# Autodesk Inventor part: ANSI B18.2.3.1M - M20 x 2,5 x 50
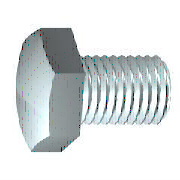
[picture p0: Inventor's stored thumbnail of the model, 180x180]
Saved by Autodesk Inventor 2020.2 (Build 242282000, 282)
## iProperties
Manager: www.cadconsulting.pl
Company: Fabian Stasiak CAD Consulting
Created: 2006-02
Part Number: ANSI B18.2.3.1M - M20 x 2,5 x 50
Material: Stal, miękka
Description: Metryczny Śruba ze łbem sześciokątnym o zmniejszonych wymiarach
Document SubType Name: Modeling
Standard: ANSI B18.2.3.1M
Designer: F.Stasiak
Standards Organization: ANSI
Language: pl-PL
Size Designation: M20 x 2,5 x 50
Categories: <MemberInstance><Categories><Category DisplayName="Mocowania" InternalName="e4da775c-781d-43d5-af7c-5136215cf5a6" Mnemonic="FSTN"><Category DisplayName="Śruby"
Density: 1 g/cm^3
Appearance: Stal
Author: F.Stasiak
Subject: Zbiór ćwiczeń. Autodesk Inventor 2020. Kurs podstawowy
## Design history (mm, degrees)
sketch "Szkic1"
  geometry: L1 (0, 13.85)-(0, 10); L2 (6.2, 10)-(50, 10); L3 (50, 10)-(50, 0); L4 (50, 0)-(-0.8, 0); L5 (-5.88, 0)-(65.24, 0) reference; L6 (-0.8, 0)-(-0.8, 13.85); L7 (-0.8, 13.85)-(0, 13.85); L8 (6.2, 10)-(4.666, 10); L9 (4.666, 10)-(0, 10); L10 (0, -1.385)-(0, 18.005) reference
  constraints: 16 end point, 2 collinear, 2 perpendicular, 1 parallel
  dimensions: "d0" = 50 distance between parallel lines of L3 L1 (= NLG); "d1" = 43.8 distance from line of L2.start L3 (= GEL); "d2" = 20 diameter of L2 L4 (= GD); "d9" = 0.8001 distance between parallel lines of L6 L1 (computed from SD); "d10" = 27.7 diameter of L7 L4 (= SD2); "d13" = 1.53373 distance of L2.start L8.end (computed from GAL); "d14" = 20 diameter of L9 L4 (= BDM)
revolve "Bryła" sketch "Szkic1" stored, may be unused: angle "d12" = 90 deg
sketch "Szkic2"
  geometry: L1 (0, 17.321)-(15, 8.66); L2 (15, 8.66)-(15, -8.66); L3 (15, -8.66)-(0, -17.321); L4 (0, -17.321)-(-15, -8.66); L5 (-15, -8.66)-(-15, 8.66); L6 (-15, 8.66)-(0, 17.321); 2 further points
  constraints: 12 end point, 1 coincident, 1 vertical, 11 other
  dimensions: "d11" = 30 distance between parallel lines of L5 L2 (= SW)
extrude "Głowica" join sketch "Szkic2" distance "d3" = 12.08 (= KOH - SD); taper "d4" = 0 deg
sketch "Szkic4"
  geometry: L1 (-12.88, 15)-(-12.88, 17.321); L2 (-12.88, 17.321)-(-11.54, 17.321); L3 (-11.54, 17.321)-(-12.88, 15); L4 (-14.088, 0)-(2.824, 0) reference; L5 (-0.8, 17.321)-(-12.88, 17.321) reference; L6 (-12.88, 8.66)-(-12.88, 17.321) reference
  constraints: 6 end point, 2 collinear, 1 perpendicular, 1 vertical
  dimensions: "d5" = 30 deg angle of L3 L1 (= ANG1); "d19" = 30 diameter of L1.start L4 (= SW0)
revolve "Faza1" sketch "Szkic4" stored, may be unused: angle "d21" = 90 deg
workplane "Work Plane1"
node "Bryła1"
node "Korpusy bryłowe"
node "Korpusy powierzchniowe"
feature "Gwint" dims "d15" = 43.8 (= GEL), "d16" = 0
chamfer "Faza2" distance "d6" = 1.53363 (= -0.5 x SPD + 0.5 x GD); stored, may be unused: second distance "d7" = 1.53373 (computed from GUL), angle "d55" = 45 deg
other parameters: "NLG" = 50 [user parameter; used in 1 equation term], "GD" = 20 (= NND) [user parameter; used in 2 equation terms], "BDM" = 20 (= NND) [user parameter; used in 1 equation term], "KOH" = 12.88 [user parameter; used in 1 equation term], "GEL" = 43.8 [user parameter; used in 2 equation terms], "SW" = 30 [user parameter; used in 3 equation terms], "SW0" = 30 (= SW) [user parameter; used in 1 equation term], "SPD" = 16.93275 (= NND - 1.2269 x PTC) [user parameter; used in 1 equation term], "SD2" = 27.7 (= SDH) [user parameter; used in 1 equation term], "SD" = 0.8 [user parameter; used in 3 equation terms], "ANG1" = 30 deg [user parameter; used in 1 equation term], "GAL" = 1.53363 (= 0.61345 x PTC) [user parameter; used in 1 equation term], "GUL" = 1.53363 (= 0.61345 x PTC) [user parameter; used in 1 equation term], "d8" = 0, "RR" = 0.1 [user parameter], "d57" = 0, "d58" = 0, "TPU" = 4 (computed from PTC) [user parameter], "WFT" = 0.8 (= SD) [user parameter], "GD1" = 16.93275 (= THREADDIA - 1.2269 x PTC) [user parameter], "SDH" = 27.7 [user parameter; used in 1 equation term], "TOA" = 30 deg [user parameter], "PTC" = 2.5 [user parameter; used in 5 equation terms], "KOH1" = 8.8 [user parameter], "GAL1" = 3.75 [user parameter], "RR1" = 0.8 [user parameter], "E0" = 34.65 (= 1.155 x SW) [user parameter]
